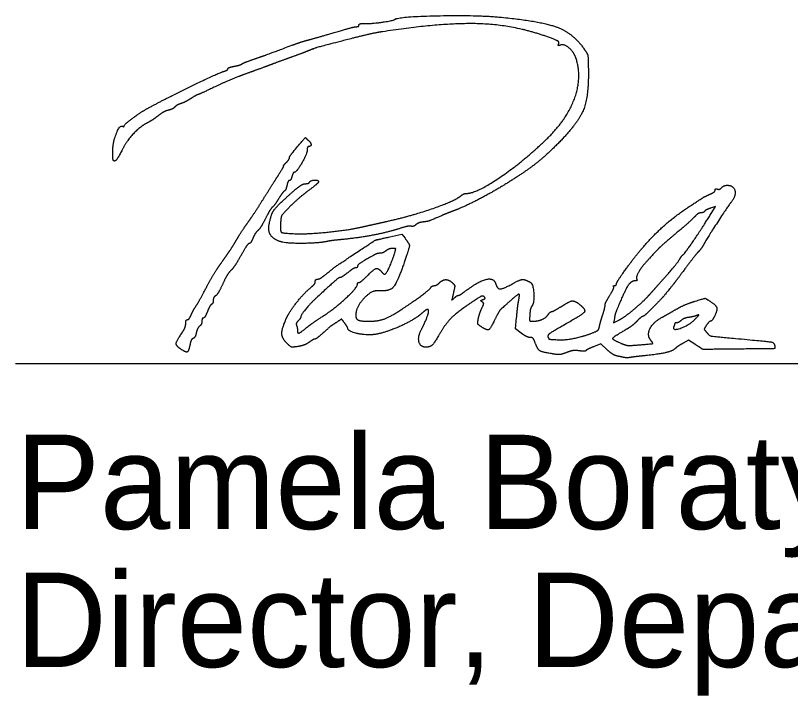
# Model space of a CAD drawing. Extents: x 0 to 39.4, y 0 to 22.
# Drawn here: x 24.528 to 25.677, y 7.305 to 8.313 of the extents above; entities that cross this region are included whole.
import ezdxf

# ---------------------------------------------------------------- set-up
doc = ezdxf.new("R2010")
doc.units = 0
for name, color, linetype in [('PV_P_Bikeway', 7, 'Continuous'), ('SH_Data', 7, 'Continuous'), ('SH_Text', 7, 'Continuous')]:
    doc.layers.add(name, color=color, linetype=linetype)

msp = doc.modelspace()

# ---------------------------------------------------------------- linework, layer by layer
at = {"layer": 'PV_P_Bikeway'}
for points in [[(25.56, 8.0208), (25.5654, 8.0298), (25.5581, 8.0272)], [(25.0827, 7.9847), (25.1007, 7.9887), (25.1054, 7.9825)], [(25.2777, 7.8419), (25.2693, 7.8482), (25.2708, 7.8653)], [(25.4157, 7.8638), (25.4146, 7.8574), (25.4233, 7.8618)], [(25.4046, 7.8175), (25.3955, 7.8258), (25.3849, 7.8217)], [(25.5365, 7.8245), (25.5258, 7.8313), (25.5175, 7.8268)]]:
    msp.add_lwpolyline(points, dxfattribs=at)
for points in [[(25.0461, 8.301), (25.0557, 8.3008), (25.0867, 8.3051), (25.0901, 8.3072)], [(25.0901, 8.3072), (25.0969, 8.3114), (25.2139, 8.3137), (25.2483, 8.3103)], [(25.2483, 8.3103), (25.3076, 8.3045), (25.3551, 8.2862), (25.3709, 8.2632)], [(25.0004, 8.2877), (25.0165, 8.2924), (25.0313, 8.2963), (25.0334, 8.2963)], [(25.0334, 8.2963), (25.0354, 8.2963), (25.0371, 8.2974), (25.0371, 8.2988)], [(25.0371, 8.2988), (25.0371, 8.3002), (25.0412, 8.3012), (25.0461, 8.301)], [(25.3208, 8.2796), (25.2703, 8.2986), (25.1623, 8.3026), (25.0719, 8.2888)], [(24.9615, 8.2765), (24.9668, 8.2779), (24.9843, 8.2829), (25.0004, 8.2877)], [(25.0719, 8.2888), (25.0627, 8.2874), (25.0427, 8.283), (25.0275, 8.2791)], [(24.9375, 8.2687), (24.9454, 8.2716), (24.9562, 8.2752), (24.9615, 8.2765)], [(25.0275, 8.2791), (24.9765, 8.2659), (24.9722, 8.2647), (24.9615, 8.2603)], [(25.3331, 8.271), (25.3341, 8.2735), (25.3307, 8.2759), (25.3208, 8.2796)], [(24.8811, 8.2481), (24.8958, 8.2532), (24.9023, 8.2555), (24.9375, 8.2687)], [(25.3355, 8.2689), (25.3329, 8.2679), (25.3322, 8.2685), (25.3331, 8.271)], [(25.3589, 8.249), (25.3557, 8.2587), (25.3412, 8.2711), (25.3355, 8.2689)], [(25.3709, 8.2632), (25.3759, 8.2559), (25.3768, 8.2516), (25.3771, 8.2337)], [(24.9387, 8.2518), (24.9288, 8.2482), (24.9137, 8.2427), (24.9051, 8.2394)], [(24.9615, 8.2603), (24.9589, 8.2592), (24.9486, 8.2554), (24.9387, 8.2518)], [(24.8517, 8.2375), (24.8567, 8.2384), (24.8618, 8.2399), (24.8631, 8.2409)], [(24.8631, 8.2409), (24.8644, 8.2419), (24.8725, 8.2451), (24.8811, 8.2481)], [(24.9051, 8.2394), (24.8965, 8.2362), (24.8803, 8.2303), (24.8691, 8.2263)], [(25.3134, 8.1278), (25.3444, 8.1572), (25.3682, 8.2207), (25.3589, 8.249)], [(24.7251, 8.1759), (24.7553, 8.1922), (24.8289, 8.2278), (24.8373, 8.2303)], [(24.8691, 8.2263), (24.8579, 8.2223), (24.8376, 8.2138), (24.8239, 8.2073)], [(24.8373, 8.2303), (24.8403, 8.2311), (24.8427, 8.2327), (24.8427, 8.2338)], [(24.8427, 8.2338), (24.8427, 8.2349), (24.8468, 8.2365), (24.8517, 8.2375)], [(25.3771, 8.2337), (25.3779, 8.1929), (25.3618, 8.1532), (25.3323, 8.1233)], [(24.8239, 8.2073), (24.8102, 8.2008), (24.7986, 8.1955), (24.798, 8.1955)], [(24.798, 8.1955), (24.7975, 8.1955), (24.793, 8.193), (24.7881, 8.1899)], [(24.7732, 8.1823), (24.77, 8.1813), (24.7659, 8.179), (24.7641, 8.1772)], [(24.7881, 8.1899), (24.7832, 8.1868), (24.7765, 8.1834), (24.7732, 8.1823)], [(24.6891, 8.1493), (24.6891, 8.1514), (24.7145, 8.1702), (24.7251, 8.1759)], [(24.7544, 8.1724), (24.7508, 8.1715), (24.7441, 8.1679), (24.7395, 8.1643)], [(24.7641, 8.1772), (24.7623, 8.1754), (24.7579, 8.1732), (24.7544, 8.1724)], [(24.7395, 8.1643), (24.7349, 8.1607), (24.7278, 8.156), (24.7236, 8.1539)], [(24.672, 8.1114), (24.6721, 8.1246), (24.6827, 8.1512), (24.6868, 8.1486)], [(24.6868, 8.1486), (24.6881, 8.1479), (24.6891, 8.1482), (24.6891, 8.1493)], [(24.7236, 8.1539), (24.7132, 8.1486), (24.6933, 8.1278), (24.6871, 8.1156)], [(24.9393, 8.1104), (24.9579, 8.1325), (24.9572, 8.1319), (24.9613, 8.1285)], [(24.9613, 8.1285), (24.9655, 8.125), (24.9665, 8.1187), (24.9627, 8.1187)], [(25.1967, 8.0491), (25.2108, 8.0491), (25.2789, 8.095), (25.3134, 8.1278)], [(25.3323, 8.1233), (25.3138, 8.1045), (25.2814, 8.0795), (25.2509, 8.0607)], [(24.6733, 8.0977), (24.6725, 8.0985), (24.6719, 8.1047), (24.672, 8.1114)], [(24.6871, 8.1156), (24.6805, 8.1027), (24.6752, 8.0959), (24.6733, 8.0977)], [(24.9603, 8.1136), (24.9603, 8.1081), (24.9444, 8.0803), (24.9412, 8.0803)], [(24.9627, 8.1187), (24.9614, 8.1187), (24.9603, 8.1164), (24.9603, 8.1136)], [(24.9291, 8.0947), (24.9318, 8.0974), (24.9339, 8.1005), (24.9339, 8.1017)], [(24.9339, 8.1017), (24.9339, 8.1029), (24.9364, 8.1068), (24.9393, 8.1104)], [(24.9164, 8.0742), (24.9219, 8.0829), (24.926, 8.0899), (24.9254, 8.0899)], [(24.9254, 8.0899), (24.9248, 8.0899), (24.9265, 8.0921), (24.9291, 8.0947)], [(24.9412, 8.0803), (24.9401, 8.0803), (24.9386, 8.0776), (24.9377, 8.0743)], [(24.8943, 8.0392), (24.9009, 8.0499), (24.9108, 8.0656), (24.9164, 8.0742)], [(24.9341, 8.0683), (24.9329, 8.0683), (24.9312, 8.0651), (24.9303, 8.0611)], [(24.9377, 8.0743), (24.9369, 8.071), (24.9353, 8.0683), (24.9341, 8.0683)], [(24.9579, 8.0635), (24.9604, 8.0635), (24.9631, 8.0646), (24.9639, 8.0659)], [(24.9771, 8.0663), (24.9771, 8.0652), (24.9704, 8.0593), (24.9621, 8.0532)], [(24.9639, 8.0659), (24.9657, 8.0688), (24.9771, 8.0691), (24.9771, 8.0663)], [(24.9255, 8.0394), (24.9412, 8.054), (24.954, 8.0635), (24.9579, 8.0635)], [(24.9303, 8.0611), (24.9295, 8.0572), (24.9277, 8.0533), (24.9264, 8.0525)], [(25.2509, 8.0607), (25.2317, 8.0489), (25.1904, 8.0279), (25.1763, 8.0228)], [(25.5573, 8.0478), (25.5616, 8.0497), (25.5651, 8.0525), (25.5651, 8.054)], [(25.5651, 8.054), (25.5651, 8.0556), (25.5667, 8.0562), (25.5685, 8.0555)], [(25.5685, 8.0555), (25.5704, 8.0548), (25.5733, 8.0558), (25.5748, 8.0577)], [(25.5748, 8.0577), (25.5764, 8.0596), (25.5801, 8.0611), (25.583, 8.0611)], [(25.583, 8.0611), (25.5925, 8.0611), (25.5962, 8.0451), (25.5888, 8.0361)], [(24.9264, 8.0525), (24.9252, 8.0518), (24.9214, 8.0466), (24.918, 8.0411)], [(24.9621, 8.0532), (24.9539, 8.0471), (24.9414, 8.0362), (24.9343, 8.029)], [(25.0767, 8.0072), (25.1137, 8.0154), (25.1799, 8.0383), (25.1885, 8.0458)], [(25.1885, 8.0458), (25.1906, 8.0476), (25.1943, 8.0491), (25.1967, 8.0491)], [(25.5283, 8.0307), (25.5473, 8.043), (25.5491, 8.0441), (25.5573, 8.0478)], [(24.8726, 8.0063), (24.8779, 8.0138), (24.8877, 8.0286), (24.8943, 8.0392)], [(24.9042, 8.0047), (24.9069, 8.0178), (24.9131, 8.0278), (24.9255, 8.0394)], [(24.918, 8.0411), (24.9146, 8.0356), (24.9104, 8.03), (24.9088, 8.0287)], [(25.4337, 7.9382), (25.456, 7.969), (25.501, 8.013), (25.5283, 8.0307)], [(25.5888, 8.0361), (25.5847, 8.0311), (25.5518, 7.9806), (25.5487, 7.9744)], [(24.9088, 8.0287), (24.9071, 8.0273), (24.9025, 8.0197), (24.8984, 8.0117)], [(24.9343, 8.029), (24.9236, 8.0181), (24.9214, 8.0144), (24.9209, 8.0062)], [(25.1763, 8.0228), (25.1717, 8.0211), (25.1647, 8.0183), (25.1607, 8.0166)], [(25.5172, 7.9579), (25.5201, 7.9599), (25.5483, 8.0014), (25.56, 8.0208)], [(25.5441, 8.0203), (25.5419, 8.0203), (25.5379, 8.0179), (25.5352, 8.0149)], [(25.5494, 8.0225), (25.5486, 8.0213), (25.5462, 8.0203), (25.5441, 8.0203)], [(25.5581, 8.0272), (25.554, 8.0258), (25.5501, 8.0237), (25.5494, 8.0225)], [(24.8984, 8.0117), (24.8944, 8.0038), (24.8893, 7.9958), (24.8872, 7.994)], [(25.1607, 8.0166), (25.1436, 8.0091), (25.1387, 8.0074), (25.1321, 8.0067)], [(25.5352, 8.0149), (25.5325, 8.0119), (25.5201, 8.0009), (25.5075, 7.9903)], [(24.8558, 7.9807), (24.8597, 7.9873), (24.8672, 7.9988), (24.8726, 8.0063)], [(24.9195, 7.9779), (24.9091, 7.9818), (24.902, 7.9942), (24.9042, 8.0047)], [(24.9209, 8.0062), (24.9201, 7.9927), (24.9241, 7.9899), (24.9447, 7.9893)], [(24.9447, 7.9893), (24.964, 7.9888), (25.0218, 7.9949), (25.0431, 7.9997)], [(25.0965, 7.9967), (25.0801, 7.9914), (25.035, 7.9829), (25.0112, 7.9806)], [(25.0431, 7.9997), (25.051, 8.0015), (25.0662, 8.0048), (25.0767, 8.0072)], [(25.1145, 8.0004), (25.1129, 8.001), (25.1048, 7.9994), (25.0965, 7.9967)], [(25.1213, 8.0026), (25.1192, 8.0008), (25.1162, 7.9998), (25.1145, 8.0004)], [(25.1321, 8.0067), (25.1282, 8.0063), (25.1234, 8.0044), (25.1213, 8.0026)], [(24.8872, 7.994), (24.885, 7.9922), (24.8817, 7.9871), (24.8799, 7.9827)], [(25.5075, 7.9903), (25.4879, 7.9738), (25.4762, 7.9624), (25.4595, 7.9435)], [(24.8428, 7.9601), (24.8461, 7.9648), (24.852, 7.9741), (24.8558, 7.9807)], [(24.8742, 7.9747), (24.8729, 7.9747), (24.8675, 7.9668), (24.8622, 7.9572)], [(24.8799, 7.9827), (24.8781, 7.9783), (24.8755, 7.9747), (24.8742, 7.9747)], [(24.9908, 7.978), (24.977, 7.975), (24.9276, 7.9749), (24.9195, 7.9779)], [(25.0112, 7.9806), (25.0028, 7.9798), (24.9936, 7.9787), (24.9908, 7.978)], [(25.0287, 7.9583), (25.0604, 7.9793), (25.0618, 7.98), (25.0827, 7.9847)], [(25.1054, 7.9825), (25.112, 7.9738), (25.1118, 7.9689), (25.1041, 7.9464)], [(25.5487, 7.9744), (25.5469, 7.971), (25.543, 7.9655), (25.54, 7.9623)], [(25.0769, 7.9638), (25.0743, 7.9619), (25.0704, 7.9603), (25.0681, 7.9603)], [(25.0868, 7.9674), (25.0839, 7.9674), (25.0794, 7.9658), (25.0769, 7.9638)], [(25.0901, 7.9609), (25.0917, 7.9667), (25.0913, 7.9675), (25.0868, 7.9674)], [(25.54, 7.9623), (25.537, 7.9591), (25.5281, 7.9477), (25.5202, 7.9371)], [(24.8293, 7.9409), (24.8334, 7.9467), (24.8395, 7.9553), (24.8428, 7.9601)], [(24.8622, 7.9572), (24.8568, 7.9475), (24.8502, 7.9375), (24.8473, 7.935)], [(24.9895, 7.9303), (25.0032, 7.9414), (25.0013, 7.94), (25.0287, 7.9583)], [(25.0584, 7.9572), (25.044, 7.9492), (25.0347, 7.9429), (25.0347, 7.9409)], [(25.0681, 7.9603), (25.0659, 7.9603), (25.0615, 7.9589), (25.0584, 7.9572)], [(25.0754, 7.9291), (25.0772, 7.9291), (25.0869, 7.9502), (25.0901, 7.9609)], [(25.482, 7.915), (25.4974, 7.9321), (25.5109, 7.9484), (25.5133, 7.9528)], [(25.5133, 7.9528), (25.5145, 7.9549), (25.5163, 7.9573), (25.5172, 7.9579)], [(24.8104, 7.9087), (24.8167, 7.9206), (24.8252, 7.9351), (24.8293, 7.9409)], [(25.0347, 7.9409), (25.0347, 7.9397), (25.0335, 7.9387), (25.0321, 7.9387)], [(25.1041, 7.9464), (25.0939, 7.9165), (25.0819, 7.9034), (25.0659, 7.9047)], [(25.4595, 7.9435), (25.4537, 7.9369), (25.4474, 7.9241), (25.4489, 7.9217)], [(24.8473, 7.935), (24.8445, 7.9324), (24.8389, 7.9233), (24.835, 7.9147)], [(24.9757, 7.9219), (24.9776, 7.9219), (24.9838, 7.9257), (24.9895, 7.9303)], [(25.0203, 7.9315), (25.0153, 7.9276), (25.0103, 7.9243), (25.0092, 7.9243)], [(25.0321, 7.9387), (25.0306, 7.9387), (25.0253, 7.9355), (25.0203, 7.9315)], [(25.0491, 7.9267), (25.0593, 7.9368), (25.0658, 7.9387), (25.0707, 7.9327)], [(25.0707, 7.9327), (25.0724, 7.9307), (25.0745, 7.9291), (25.0754, 7.9291)], [(25.4187, 7.9149), (25.4187, 7.9163), (25.4255, 7.9268), (25.4337, 7.9382)], [(25.5202, 7.9371), (25.5123, 7.9264), (25.5047, 7.9162), (25.5032, 7.9144)], [(24.9669, 7.9107), (24.9699, 7.9131), (24.9723, 7.9166), (24.9723, 7.9185)], [(24.9723, 7.9185), (24.9723, 7.9204), (24.9738, 7.9219), (24.9757, 7.9219)], [(25.0092, 7.9243), (25.0073, 7.9243), (24.9988, 7.917), (24.9735, 7.8938)], [(25.0347, 7.914), (25.0347, 7.9157), (25.0358, 7.9171), (25.0371, 7.9171)], [(25.0371, 7.9171), (25.0384, 7.9171), (25.0438, 7.9214), (25.0491, 7.9267)], [(25.1487, 7.9123), (25.1505, 7.9123), (25.1537, 7.9141), (25.1559, 7.9162)], [(25.1559, 7.9162), (25.1609, 7.9212), (25.1708, 7.9212), (25.1758, 7.9163)], [(25.1758, 7.9163), (25.1789, 7.9131), (25.1792, 7.9107), (25.1771, 7.9015)], [(25.1939, 7.9036), (25.2141, 7.9188), (25.2368, 7.9244), (25.2398, 7.915)], [(25.2636, 7.9146), (25.2756, 7.9212), (25.2828, 7.9219), (25.291, 7.9173)], [(25.291, 7.9173), (25.2954, 7.9149), (25.2971, 7.8869), (25.2932, 7.8817)], [(25.4466, 7.9195), (25.4403, 7.9195), (25.4307, 7.9043), (25.4187, 7.8751)], [(25.4489, 7.9217), (25.4496, 7.9205), (25.4486, 7.9195), (25.4466, 7.9195)], [(24.7949, 7.8811), (24.7971, 7.8844), (24.8041, 7.8968), (24.8104, 7.9087)], [(24.835, 7.9147), (24.8311, 7.9061), (24.8263, 7.8982), (24.8245, 7.8972)], [(24.9288, 7.8624), (24.9333, 7.8729), (24.9565, 7.9023), (24.9669, 7.9107)], [(24.9887, 7.8705), (25.0042, 7.8809), (25.0347, 7.9097), (25.0347, 7.914)], [(25.0659, 7.9047), (25.0555, 7.9056), (25.0323, 7.8803), (25.0323, 7.868)], [(25.1007, 7.8774), (25.1193, 7.8898), (25.1417, 7.9065), (25.1434, 7.9092)], [(25.1434, 7.9092), (25.1445, 7.9109), (25.1469, 7.9123), (25.1487, 7.9123)], [(25.2398, 7.915), (25.2422, 7.9074), (25.2503, 7.9073), (25.2636, 7.9146)], [(25.409, 7.898), (25.4128, 7.9043), (25.4153, 7.9101), (25.4146, 7.9109)], [(25.4146, 7.9109), (25.4138, 7.9117), (25.4144, 7.9123), (25.4159, 7.9123)], [(25.4159, 7.9123), (25.4175, 7.9123), (25.4187, 7.9135), (25.4187, 7.9149)], [(25.4664, 7.8975), (25.4696, 7.901), (25.4766, 7.9089), (25.482, 7.915)], [(25.5032, 7.9144), (25.4899, 7.898), (25.4854, 7.8928), (25.4735, 7.8807)], [(24.8245, 7.8972), (24.8226, 7.8961), (24.8211, 7.8932), (24.8211, 7.8907)], [(24.9735, 7.8938), (24.9644, 7.8854), (24.9507, 7.8683), (24.9507, 7.8654)], [(25.1771, 7.9015), (25.1747, 7.8913), (25.1748, 7.8908), (25.1786, 7.8942)], [(25.1786, 7.8942), (25.1809, 7.8963), (25.1835, 7.8979), (25.1845, 7.8979)], [(25.1845, 7.8979), (25.1854, 7.8979), (25.1897, 7.9005), (25.1939, 7.9036)], [(25.2226, 7.8958), (25.2208, 7.8976), (25.2149, 7.8949), (25.2024, 7.8864)], [(25.2209, 7.8917), (25.2239, 7.8928), (25.2244, 7.894), (25.2226, 7.8958)], [(25.2738, 7.8901), (25.2756, 7.8996), (25.273, 7.9), (25.2637, 7.8918)], [(25.4019, 7.8832), (25.4019, 7.8851), (25.4051, 7.8917), (25.409, 7.898)], [(25.4463, 7.8786), (25.4542, 7.8855), (25.4633, 7.8939), (25.4664, 7.8975)], [(25.5356, 7.8893), (25.5497, 7.8936), (25.5509, 7.8936), (25.5567, 7.8897)], [(24.8186, 7.8846), (24.8172, 7.8838), (24.8144, 7.8789), (24.8124, 7.8737)], [(24.8211, 7.8907), (24.8211, 7.8882), (24.82, 7.8855), (24.8186, 7.8846)], [(25.2024, 7.8864), (25.1826, 7.8729), (25.1654, 7.8559), (25.1571, 7.8415)], [(25.2197, 7.8882), (25.2175, 7.8896), (25.2178, 7.8905), (25.2209, 7.8917)], [(25.219, 7.8783), (25.2219, 7.8846), (25.222, 7.8868), (25.2197, 7.8882)], [(25.2637, 7.8918), (25.2477, 7.8777), (25.244, 7.8733), (25.2385, 7.862)], [(25.2708, 7.8653), (25.2716, 7.8746), (25.2729, 7.8858), (25.2738, 7.8901)], [(25.2932, 7.8817), (25.2919, 7.8801), (25.2906, 7.8744), (25.2903, 7.8691)], [(25.3645, 7.8841), (25.3742, 7.8765), (25.3674, 7.8686), (25.3358, 7.8508)], [(25.3363, 7.8811), (25.3493, 7.8893), (25.3569, 7.8901), (25.3645, 7.8841)], [(25.3984, 7.8691), (25.4004, 7.8751), (25.4019, 7.8814), (25.4019, 7.8832)], [(25.5063, 7.8767), (25.5142, 7.8812), (25.5274, 7.8869), (25.5356, 7.8893)], [(25.5567, 7.8897), (25.5663, 7.8834), (25.5687, 7.876), (25.5641, 7.867)], [(24.7881, 7.8685), (24.7896, 7.8721), (24.7927, 7.8778), (24.7949, 7.8811)], [(24.8124, 7.8737), (24.8103, 7.8685), (24.8076, 7.8643), (24.8065, 7.8643)], [(24.9571, 7.8482), (24.9647, 7.8543), (24.9699, 7.858), (24.9887, 7.8705)], [(25.0523, 7.8595), (25.0653, 7.8595), (25.0844, 7.8666), (25.1007, 7.8774)], [(25.1327, 7.8733), (25.1231, 7.8641), (25.0844, 7.8453), (25.0659, 7.8409)], [(25.1297, 7.8475), (25.1339, 7.8552), (25.1403, 7.8715), (25.1403, 7.8742)], [(25.1403, 7.8742), (25.1403, 7.8773), (25.1364, 7.8768), (25.1327, 7.8733)], [(25.2139, 7.8627), (25.2147, 7.8669), (25.217, 7.8739), (25.219, 7.8783)], [(25.3172, 7.869), (25.3191, 7.8717), (25.3216, 7.8739), (25.3228, 7.8739)], [(25.3228, 7.8739), (25.324, 7.8739), (25.3301, 7.8772), (25.3363, 7.8811)], [(25.4187, 7.8751), (25.4176, 7.8725), (25.4162, 7.8674), (25.4157, 7.8638)], [(25.4233, 7.8618), (25.428, 7.8643), (25.4384, 7.8718), (25.4463, 7.8786)], [(25.4735, 7.8807), (25.466, 7.873), (25.459, 7.8667), (25.4579, 7.8667)], [(25.4868, 7.8656), (25.4896, 7.8672), (25.4984, 7.8721), (25.5063, 7.8767)], [(24.7803, 7.8562), (24.7803, 7.8594), (24.7814, 7.8619), (24.7828, 7.8619)], [(24.7828, 7.8619), (24.7841, 7.8619), (24.7865, 7.8649), (24.7881, 7.8685)], [(24.8043, 7.8598), (24.8043, 7.8573), (24.8028, 7.854), (24.8009, 7.8524)], [(24.8065, 7.8643), (24.8053, 7.8643), (24.8043, 7.8623), (24.8043, 7.8598)], [(24.9305, 7.8267), (24.9229, 7.8343), (24.9223, 7.8472), (24.9288, 7.8624)], [(24.947, 7.8602), (24.9449, 7.8582), (24.9438, 7.8549), (24.9446, 7.853)], [(24.9507, 7.8654), (24.9507, 7.8646), (24.949, 7.8623), (24.947, 7.8602)], [(25.0157, 7.857), (25.0113, 7.8628), (25.0112, 7.8628), (25.0044, 7.8583)], [(25.0323, 7.868), (25.0323, 7.8628), (25.0401, 7.8595), (25.0523, 7.8595)], [(25.2185, 7.8512), (25.2136, 7.8545), (25.2128, 7.8564), (25.2139, 7.8627)], [(25.2385, 7.862), (25.2318, 7.8483), (25.227, 7.8456), (25.2185, 7.8512)], [(25.2903, 7.8691), (25.2898, 7.8615), (25.2905, 7.8595), (25.2936, 7.8595)], [(25.2936, 7.8595), (25.3019, 7.8595), (25.3139, 7.8644), (25.3172, 7.869)], [(25.3936, 7.8521), (25.3943, 7.8555), (25.3965, 7.8632), (25.3984, 7.8691)], [(25.4493, 7.8598), (25.4457, 7.8559), (25.4376, 7.8498), (25.4313, 7.8462)], [(25.4579, 7.8667), (25.4568, 7.8667), (25.453, 7.8636), (25.4493, 7.8598)], [(25.4697, 7.8313), (25.4636, 7.8387), (25.4734, 7.8584), (25.4868, 7.8656)], [(25.5037, 7.8514), (25.5012, 7.8448), (25.5267, 7.8538), (25.5351, 7.8624)], [(25.5147, 7.8607), (25.5125, 7.8587), (25.5095, 7.8571), (25.5079, 7.8571)], [(25.5257, 7.8652), (25.5219, 7.8647), (25.5169, 7.8627), (25.5147, 7.8607)], [(25.5375, 7.868), (25.5349, 7.867), (25.5296, 7.8657), (25.5257, 7.8652)], [(25.5351, 7.8624), (25.5406, 7.868), (25.5412, 7.8693), (25.5375, 7.868)], [(25.5581, 7.8595), (25.557, 7.8595), (25.5544, 7.8569), (25.5523, 7.8537)], [(25.5641, 7.867), (25.562, 7.8629), (25.5593, 7.8595), (25.5581, 7.8595)], [(24.7745, 7.842), (24.7777, 7.8467), (24.7803, 7.8531), (24.7803, 7.8562)], [(24.8009, 7.8524), (24.799, 7.8509), (24.7967, 7.8463), (24.7959, 7.8424)], [(24.9446, 7.853), (24.9453, 7.8511), (24.9459, 7.848), (24.9459, 7.8461)], [(24.9459, 7.8461), (24.9459, 7.8413), (24.9493, 7.8419), (24.9571, 7.8482)], [(25.0044, 7.8583), (24.9962, 7.853), (24.9937, 7.8509), (24.9824, 7.8409)], [(25.0203, 7.8496), (25.0202, 7.8504), (25.0182, 7.8537), (25.0157, 7.857)], [(25.0659, 7.8409), (25.0531, 7.8378), (25.0205, 7.844), (25.0203, 7.8496)], [(25.1365, 7.8211), (25.1281, 7.8211), (25.124, 7.8369), (25.1297, 7.8475)], [(25.3358, 7.8508), (25.3226, 7.8434), (25.3163, 7.8386), (25.3172, 7.8364)], [(25.381, 7.8414), (25.3898, 7.8448), (25.3927, 7.8472), (25.3936, 7.8521)], [(25.5051, 7.8561), (25.5051, 7.8556), (25.5045, 7.8534), (25.5037, 7.8514)], [(25.5079, 7.8571), (25.5064, 7.8571), (25.5051, 7.8567), (25.5051, 7.8561)], [(25.5523, 7.8537), (25.5488, 7.8483), (25.5488, 7.8475), (25.5526, 7.8428)], [(24.7728, 7.8183), (24.7658, 7.8232), (24.7663, 7.8299), (24.7745, 7.842)], [(24.7959, 7.8424), (24.795, 7.8384), (24.7929, 7.8346), (24.7911, 7.834)], [(24.9824, 7.8409), (24.9776, 7.8366), (24.9728, 7.8331), (24.9717, 7.8331)], [(25.1571, 7.8415), (25.1489, 7.8274), (25.1426, 7.8211), (25.1365, 7.8211)], [(25.2907, 7.8355), (25.2881, 7.8355), (25.2822, 7.8384), (25.2777, 7.8419)], [(25.2982, 7.8277), (25.2963, 7.8329), (25.2938, 7.8355), (25.2907, 7.8355)], [(25.3172, 7.8364), (25.3185, 7.833), (25.3192, 7.8328), (25.3311, 7.8321)], [(25.3311, 7.8321), (25.3416, 7.8315), (25.3678, 7.8364), (25.381, 7.8414)], [(25.4313, 7.8462), (25.4134, 7.8357), (25.4124, 7.8325), (25.4253, 7.8269)], [(25.5526, 7.8428), (25.5563, 7.8382), (25.5612, 7.8372), (25.5951, 7.8341)], [(24.7865, 7.8248), (24.7847, 7.815), (24.7805, 7.813), (24.7728, 7.8183)], [(24.7911, 7.834), (24.7894, 7.8333), (24.7873, 7.8292), (24.7865, 7.8248)], [(24.9467, 7.8221), (24.938, 7.8208), (24.9358, 7.8214), (24.9305, 7.8267)], [(24.9632, 7.8284), (24.9596, 7.8258), (24.9522, 7.823), (24.9467, 7.8221)], [(24.9717, 7.8331), (24.9706, 7.8331), (24.9668, 7.831), (24.9632, 7.8284)], [(25.3235, 7.8112), (25.3085, 7.8136), (25.3017, 7.8181), (25.2982, 7.8277)], [(25.4253, 7.8269), (25.4322, 7.824), (25.4386, 7.8234), (25.4521, 7.8245)], [(25.4521, 7.8245), (25.4717, 7.8261), (25.4734, 7.8267), (25.4697, 7.8313)], [(25.5175, 7.8268), (25.5128, 7.8243), (25.5076, 7.8208), (25.5057, 7.819)], [(25.5831, 7.8181), (25.5474, 7.8177), (25.547, 7.8178), (25.5365, 7.8245)], [(25.5951, 7.8341), (25.6442, 7.8295), (25.6525, 7.828), (25.6534, 7.8232)], [(25.3447, 7.8131), (25.3377, 7.8103), (25.3321, 7.8098), (25.3235, 7.8112)], [(25.3635, 7.8157), (25.3578, 7.8164), (25.3505, 7.8154), (25.3447, 7.8131)], [(25.3736, 7.816), (25.3732, 7.8151), (25.3687, 7.815), (25.3635, 7.8157)], [(25.3849, 7.8217), (25.3791, 7.8195), (25.374, 7.8169), (25.3736, 7.816)], [(25.4193, 7.8081), (25.4163, 7.8087), (25.4097, 7.813), (25.4046, 7.8175)], [(25.5057, 7.819), (25.502, 7.8152), (25.4805, 7.8104), (25.4571, 7.808)], [(25.6534, 7.8232), (25.6542, 7.819), (25.6523, 7.8188), (25.5831, 7.8181)], [(25.4295, 7.8059), (25.4269, 7.8065), (25.4223, 7.8074), (25.4193, 7.8081)], [(25.4379, 7.8056), (25.4359, 7.8052), (25.4322, 7.8054), (25.4295, 7.8059)], [(25.4571, 7.808), (25.4485, 7.8071), (25.4399, 7.806), (25.4379, 7.8056)]]:
    msp.add_open_spline(points, degree=2, dxfattribs=at)
at = {"layer": 'SH_Data'}
msp.add_line((24.5279, 7.7968), (28.0279, 7.7968), dxfattribs=at)

# ---------------------------------------------------------------- texts
at = {"layer": 'SH_Text'}
for s, p in [('Pamela Boratyn', (24.5282, 7.5514)), ('Director, Department of Transportation', (24.5279, 7.3468))]:
    msp.add_text(s, height=0.14, dxfattribs=at).set_placement(p)

doc.saveas('drawing.dxf')
